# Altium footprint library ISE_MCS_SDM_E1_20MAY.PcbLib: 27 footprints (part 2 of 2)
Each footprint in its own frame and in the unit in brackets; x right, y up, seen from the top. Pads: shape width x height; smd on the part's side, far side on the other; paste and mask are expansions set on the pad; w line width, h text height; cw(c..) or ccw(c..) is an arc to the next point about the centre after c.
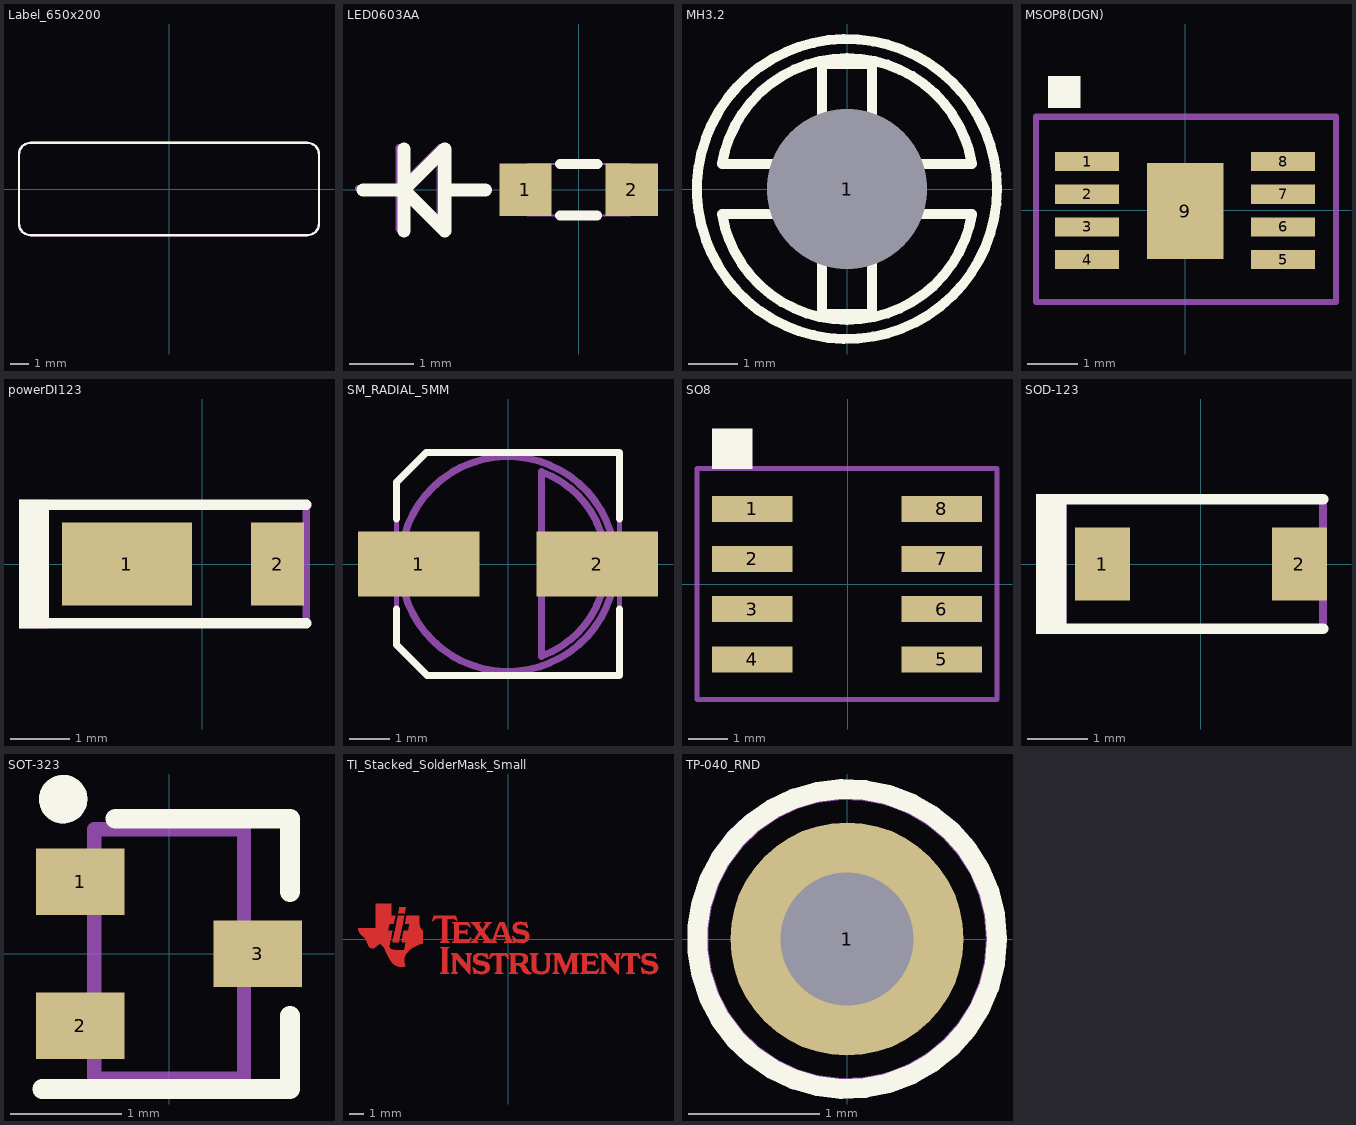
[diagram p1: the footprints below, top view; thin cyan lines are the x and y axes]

## Label_650x200 [mil] "Thermal Transfer Label"
height 1
pads (1):
  round 1 on Mech13: 0(0,0)
Top Overlay:
  lines w5: -325,-75 ccw(c-300,-75) -300,-100 300,-100 ccw(c300,-75) 325,-75 325,75 ccw(c300,75) 300,100 -300,100 ccw(c-300,75) -325,75 -325,-75
Mechanical 5:
  lines w5: -325,-75 ccw(c-300,-75) -300,-100 300,-100 ccw(c300,-75) 325,-75 325,75 ccw(c300,75) 300,100 -300,100 ccw(c-300,75) -325,75 -325,-75
  text ".Designator" at -60,-20 h40
3D body: height 1, standoff 0, extent -325.51,-100.51 325.51,100.51

## LED0603AA [mil]
height 35.43
pads (2):
  rect 32x32 smd: 1(-32.48,0) 2(32.48,0)
Top Overlay:
  lines w6: -11.42,-15.75 11.42,-15.75 ; -11.42,15.75 11.42,15.75
  lines w8: -131.79,-0.04 -106.79,-0.04 ; -106.79,-25.04 -106.79,24.96 ; -81.79,-0.04 -56.79,-0.04 ; -106.79,-0.04 -81.79,24.96 -81.79,-25.04 -106.79,-0.04
Mechanical 15:
  lines w1: -31.5,-15.75 31.5,-15.75 31.5,15.75 -31.5,15.75 -31.5,-15.75
  lines w3.94: -134.79,0.96 -109.79,0.96 ; -109.79,-24.04 -109.79,25.96 ; -84.79,0.96 -59.79,0.96 ; -109.79,0.96 -84.79,25.96 -84.79,-24.04 -109.79,0.96

## MH3.2 [mil]
height 80
pads (1):
  round 20 / inner round 142 / far side round 20 hole 128 unplated: 1(0,0)
Top Overlay:
  circle w8: c0,0 r120
  lines w8: -100,-20 -20,-20 -20,-100 20,-100 20,-20 100,-20 ; -100.02,-19.91 ccw(c0,-3.35) 99.99,-20.08 ; -100,20 -20,20 -20,100 20,100 20,20 100,20 ; -99.99,20.09 cw(c0,3.36) 100.02,19.92

## MSOP8(DGN) [mil]
pads (9):
  rect 50x15 smd: 1(-77,38) 2(-77,12.4) 3(-77,-13.2) 4(-77,-38.8) 5(76.6,-38.8) 6(76.6,-13.2) 7(76.6,12.4) 8(76.6,38)
  rect 60x75 smd: 9(0,-0.8)
Top Overlay:
  region: -107.5,105 -82.5,105 -82.5,80 -107.5,80
Mechanical 5:
  lines w5: -117,-72 118,-72 118,73 -117,73 -117,-72
  text "*" at -105,30 h30
  text ".Designator" at -73,-20 h40

## powerDI123 [mm] "Diodes Inc recommended land pattern, document number DS30628 Rev. 6-2"
height 1
pads (2):
  rect 2.2x1.4 smd: 1(-1.275,0)
  rect 0.9x1.4 smd: 2(1.275,0)
Top Overlay:
  rectangle: -3.099,-1.092 -2.591,1.092
  lines w0.178: -2.946,-1.003 1.759,-1.003 ; -2.946,1.003 1.759,1.003
Mechanical 5:
  rectangle: -3.099,-1.092 -2.591,1.092
  lines w0.127: -2.946,-1.003 1.759,-1.003 1.759,1.003 -2.946,1.003
  text ".Designator" at -2.35,-0.275 h0.76
3D body: height 1, standoff 0, extent -2.375,-0.965 1.525,0.965

## SM_RADIAL_5MM [mm] "Nichicon 5x5.8"
height 6.1
pads (2):
  rect 3x1.6 smd: 1(-2.2,0) 2(2.2,0)
Top Overlay:
  lines w0.178: -2.75,-1.108 -2.75,-1.992 -1.992,-2.75 2.75,-2.75 2.75,-1.108 ; -2.75,1.108 -2.75,2.019 -2.019,2.75 2.75,2.75 2.75,1.118
Mechanical 5:
  lines w0.127: -2.75,-1.992 -2.75,2.019 -2.019,2.75 2.75,2.75 2.75,-2.75 -1.992,-2.75 -2.75,-1.992
  text ".Designator" at -1.9,-0.5 h1.02
Mechanical 13:
  circle w0.178: c0,0 r2.65
  lines w0.178: 0.827,-2.273 ccw(c0,0) 0.827,2.273 0.827,-2.273
3D body: height 1, standoff 0, extent -2.751,-2.751 2.751,2.751
3D body: height 6.1, standoff 1, extent -2.658,-2.658 2.658,2.658
3D body: height 6.1, standoff 6, extent 0.827,-2.277 2.432,2.277

## SO8 [mil]
pads (8):
  rect 80x26 smd: 1(-95,75) 2(-95,25) 3(-95,-25) 4(-95,-75) 5(94,-75) 6(94,-25) 7(94,25) 8(94,75)
Top Overlay:
  region: -95,115 -95,155 -135,155 -135,115
Mechanical 5:
  lines w5: -150,-115 -150,115 149,115 149,-115 -150,-115
  text "*" at -55.9,51.4 h30
  text ".Designator" at -60,-20 h40

## SOD-123 [mm] "On Semi recommended land pattern"
height 1.35
pads (2):
  rect 0.915x1.22 smd: 1(-1.637,0) 2(1.637,0)
Top Overlay:
  rectangle: -2.743,-1.168 -2.235,1.168
  lines w0.178: -2.413,-1.079 2.032,-1.079 ; -2.413,1.079 2.032,1.079
Mechanical 5:
  rectangle: -2.743,-1.168 -2.235,1.168
  lines w0.127: -2.413,-1.079 2.032,-1.079 2.032,1.079 -2.413,1.079
  text ".Designator" at -1.956,-0.33 h0.76
3D body: height 1.35, standoff 0, extent -1.932,-0.9 1.932,0.9

## SOT-323 [mm] "Zetex recommended land pattern.  March 2007"
height 1.1
pads (3):
  rect 0.8x0.6 smd: 1(-0.8,0.65) 2(-0.8,-0.65) 3(0.8,0)
Top Overlay:
  circle w0.254: c-0.955,1.397 r0.092
  lines w0.178: -1.143,-1.219 1.092,-1.219 1.092,-0.559 ; -0.483,1.219 1.092,1.219 1.092,0.559
Mechanical 5:
  circle w0.254: c-0.955,1.397 r0.092
  lines w0.127: -1.125,-0.8 -0.975,-0.8 -0.935,-0.8 -0.884,-0.8 -0.725,-0.8 -0.675,-0.8 -0.675,-0.5 -0.725,-0.5 -0.884,-0.5 -0.935,-0.5 -0.975,-0.5 -1.125,-0.5 -1.125,-0.8 ; -1.125,0.5 -0.975,0.5 -0.935,0.5 -0.884,0.5 -0.725,0.5 -0.675,0.5 -0.675,0.8 -0.725,0.8 -0.884,0.8 -0.935,0.8 -0.975,0.8 -1.125,0.8 -1.125,0.5 ; -0.675,-1.125 0.675,-1.125 0.675,1.125 -0.675,1.125 -0.675,-1.125 ; 0.675,-0.15 0.675,0.15 0.725,0.15 0.884,0.15 0.935,0.15 0.975,0.15 1.125,0.15 1.125,-0.15 0.975,-0.15 0.935,-0.15 0.884,-0.15 0.725,-0.15 0.675,-0.15
  text ".Designator" at -0.25,0.925 h0.51
3D body: height 1.13, standoff 0.02, extent -1.125,-1.125 1.125,1.125

## TI_Stacked_SolderMask_Small [mil]
pads (1):
  rect 0x0 smd paste-125 mask-125: 0(0,0)
Top Layer:
  drawing of 18 lines, arcs and shapes, not listed

## TP-040_RND [mil]
pads (1):
  round 70 / inner round 62 / far side round 62 hole 40: 1(0,0)
Top Overlay:
  circle w6: c0,0 r45
Mechanical 5:
  circle w6: c0,0 r44.72
  text ".Designator" at -25,-30 h60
